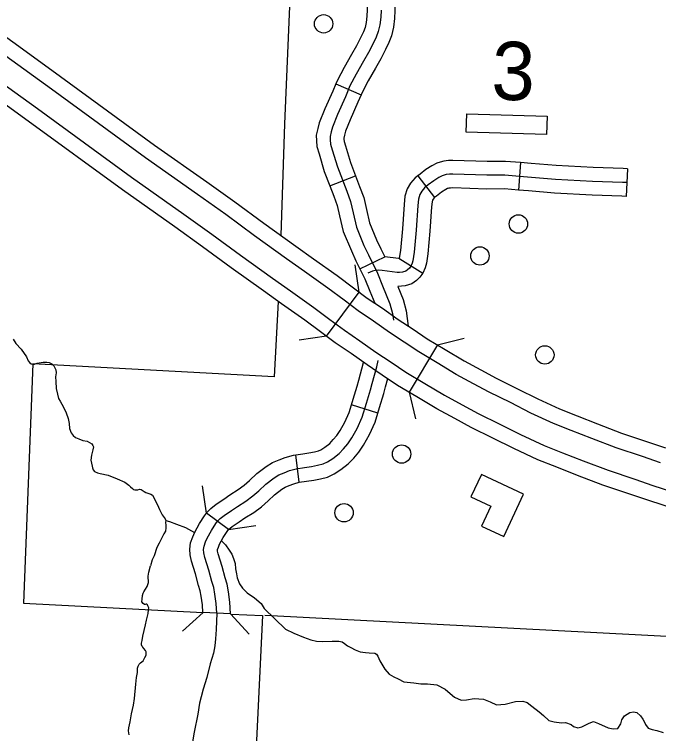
# Model space of a CAD drawing. Extents: x 653372 to 905732, y 627442 to 787275.
# Drawn here: x 663412 to 666917, y 758847 to 762760 of the extents above; entities that cross this region are included whole.
import ezdxf

# ---------------------------------------------------------------- set-up
doc = ezdxf.new("R2010")
doc.units = 0
for name, color, linetype in [('19', 7, 'Continuous'), ('32', 7, 'Continuous'), ('33', 7, 'Continuous'), ('35', 7, 'Continuous'), ('36', 7, 'Continuous'), ('38', 7, 'Continuous'), ('45', 7, 'Continuous'), ('5', 7, 'Continuous'), ('56', 7, 'Continuous'), ('58', 7, 'Continuous'), ('6', 7, 'Continuous')]:
    doc.layers.add(name, color=color, linetype=linetype)

msp = doc.modelspace()

# ---------------------------------------------------------------- linework, layer by layer
at = {"layer": '19'}
for points in [[(663252, 762717.9), (663415.2, 762600.8), (663662.9, 762422.5), (664175.1, 762049), (664458.2, 761848.3), (664611.4, 761739), (664768.3, 761624.5), (664942.4, 761499.1), (665039.1, 761430.2), (665167.9, 761339), (665257.6, 761272.5), (665332, 761216.4), (665414.1, 761161.3), (665500.5, 761099.8), (665580.9, 761046.7), (665657.5, 760994.8), (665755.8, 760936.2), (665858.5, 760874.4), (665950.3, 760825), (666034.1, 760779.8), (666149.2, 760723.4), (666259.3, 760667.5), (666378.6, 760612.8), (666473.3, 760575.2), (666583.9, 760531.6), (666714.6, 760481.9), (666857.2, 760434.4), (666954.2, 760401)], [(666927.3, 760320.4), (666829.9, 760353.9), (666686, 760401.8), (666553.2, 760452.4), (666442.1, 760496.1), (666345.1, 760534.6), (666222.3, 760590.9), (666111.2, 760647.4), (665995.3, 760704.2), (665910, 760750.1), (665816.4, 760800.5), (665712.1, 760863.3), (665611.8, 760923), (665533.6, 760976.1), (665452.5, 761029.7), (665365.7, 761091.4), (665282.7, 761147.1), (665206.7, 761204.5), (665118, 761270.2), (664989.8, 761360.9), (664892.9, 761430), (664718.4, 761555.7), (664561.7, 761670.1), (664409, 761779), (664125.5, 761980), (663613.1, 762353.7), (663365.6, 762531.7)], [(663289.7, 762426.2), (663536.8, 762248.4), (664049.6, 761874.4), (664333.6, 761673.1), (664485.6, 761564.7), (664642.1, 761450.4), (664817.2, 761324.3), (664914.5, 761255), (665041.7, 761164.9), (665128.8, 761100.4), (665207.2, 761041.2), (665291.8, 760984.4), (665378.9, 760922.5), (665461.2, 760868.1), (665542, 760813.3), (665645.3, 760751.7), (665752.1, 760687.5), (665848.4, 760635.7), (665935.8, 760588.6), (666053.2, 760531), (666165.8, 760473.8), (666294, 760415.1), (666394.3, 760375.2), (666506.3, 760331.1), (666642.4, 760279.3), (666788.2, 760230.8), (666886.2, 760197), (667134.5, 760117)], [(667108.6, 760036), (666859.3, 760116.4), (666761, 760150.3), (666613.8, 760199.2), (666475.6, 760251.9), (666363, 760296.2), (666260.6, 760336.9), (666128.8, 760397.3), (666015.2, 760455), (665896.9, 760513), (665808.1, 760560.8), (665710, 760613.6), (665601.7, 760678.8), (665496.4, 760741.5), (665413.9, 760797.4), (665330.9, 760852.4), (665243.5, 760914.5), (665157.9, 760971.9), (665077.9, 761032.3), (664991.9, 761096), (664865.3, 761185.7), (664767.7, 761255.2), (664592.2, 761381.6), (664435.8, 761495.7), (664284.4, 761603.8), (664000, 761805.4), (663486.9, 762179.6), (663240.1, 762357.1)]]:
    msp.add_lwpolyline(points, dxfattribs=at)
at = {"layer": '32'}
for p, q in [((665160.9, 762381.1), (665298.6, 762321.4)), ((666166.4, 761953.4), (666154.8, 761803.9)), ((665128.6, 761826.9), (665268.6, 761880.8)), ((665606.5, 761881.7), (665698, 761762.8)), ((665292.4, 761374.5), (665427.1, 761440.4)), ((665509, 761430.4), (665634.8, 761352.3)), ((665389.2, 760590.1), (665246, 760634.6)), ((664961.8, 760214.6), (664943, 760363.4)), ((664576.1, 759956.4), (664456.3, 760045.6)), ((664588.3, 759498.1), (664437.5, 759505.3))]:
    msp.add_line(p, q, dxfattribs=at)
for points in [[(665480.6, 762842.2), (665481, 762834.1), (665481.8, 762781.6), (665479.9, 762738.1), (665474.6, 762689.5), (665463.4, 762643.9), (665448.9, 762606.7), (665431.5, 762569.2), (665405, 762517.3), (665376.8, 762467.6), (665337, 762398.7), (665305.8, 762338.2), (665298.6, 762321.4)], [(665330.8, 762834.4), (665331.1, 762829.1), (665331.8, 762783.8), (665330.2, 762749.6), (665326.5, 762715.5), (665320.1, 762689.2), (665310.9, 762665.6), (665296.6, 762634.9), (665272.9, 762588.4), (665246.6, 762542.1), (665205.4, 762470.6), (665170.2, 762402.5), (665160.9, 762381.1)], [(665406.8, 762782.7), (665405.1, 762743.8), (665400.5, 762702.5), (665391.8, 762666.5), (665379.9, 762636.2), (665364, 762602), (665339, 762552.8), (665311.7, 762504.8), (665271.2, 762434.7), (665238, 762370.3), (665212.7, 762311.8), (665170.8, 762215.9), (665141.9, 762146.9), (665135.6, 762120.8), (665129.3, 762094.6), (665129.9, 762077), (665131.9, 762054.4), (665141.4, 762022.9), (665169.4, 761929.8), (665220.3, 761797.5), (665240.5, 761741.4), (665254.6, 761680.6), (665273.1, 761602.1), (665314.1, 761503), (665338.3, 761451.4), (665387.3, 761351.1), (665415.3, 761282.1), (665455.3, 761184.5), (665469.3, 761132.6), (665474.4, 761096.1)], [(665160.9, 762381.1), (665143.9, 762341.7), (665101.9, 762245.4), (665070.3, 762170.3), (665062.7, 762138.2), (665054, 762102.3), (665055, 762072.4), (665057.9, 762040.1), (665069.6, 762001.3), (665098.3, 761905.5), (665128.6, 761826.9)], [(665298.6, 762321.4), (665281.4, 762281.9), (665239.8, 762186.4), (665213.4, 762123.5), (665208.5, 762103.3), (665204.6, 762086.9), (665204.8, 762081.7), (665205.9, 762068.8), (665213.3, 762044.4), (665240.4, 761954.1), (665268.6, 761880.8)], [(666166.4, 761953.4), (666083.3, 761959.8), (665983.7, 761959.2), (665797.9, 761965.3), (665774.8, 761964.5), (665748.4, 761961.8), (665729.2, 761956.6), (665710, 761950.7), (665683.2, 761936), (665650.7, 761914.9), (665619, 761891.3), (665606.5, 761881.7)], [(665268.6, 761880.8), (665290.5, 761823.7), (665312.6, 761762.7), (665327.6, 761697.7), (665344.7, 761625.2), (665382.7, 761533.2), (665405.9, 761483.8), (665427.1, 761440.4)], [(666160.6, 761878.6), (666080.7, 761884.8), (665982.7, 761884.1), (665798, 761890.3), (665780.1, 761889.6), (665762, 761887.8), (665750, 761884.6), (665739.3, 761881.3), (665721.7, 761871.6), (665693.6, 761853.3), (665664.2, 761831.5), (665644, 761815.9), (665629.1, 761798.4), (665618.4, 761780.2), (665610.5, 761755.2), (665607, 761719.4), (665598.3, 761586.6), (665586.9, 761466.6), (665580.1, 761419.6), (665576.6, 761405.3), (665569.6, 761389.9), (665562.1, 761379.4), (665551.6, 761369.5), (665541.9, 761362.6), (665523.7, 761357.2), (665507.5, 761355.3), (665493.8, 761356.3), (665413.9, 761366.5), (665394.8, 761368.3), (665375, 761366.5), (665361.1, 761362.7), (665334.5, 761352.7)], [(665606.5, 761881.7), (665592, 761870.5), (665567.8, 761842), (665549.5, 761810.9), (665536.6, 761770.4), (665532.3, 761725.5), (665523.5, 761592.6), (665512.4, 761475.6), (665506.3, 761433.7), (665505.6, 761430.6), (665509, 761430.4)], [(665128.6, 761826.9), (665150, 761771.3), (665168.5, 761720.1), (665181.6, 761663.6), (665201.5, 761579.1), (665245.4, 761472.7), (665270.6, 761419), (665315.1, 761328)], [(666154.8, 761803.9), (666078, 761809.8), (665981.8, 761809.1), (665798.1, 761815.2), (665785.3, 761814.8), (665775.7, 761813.8), (665770.7, 761812.5), (665768.7, 761811.8), (665760.2, 761807.2), (665736.5, 761791.8), (665709.5, 761771.6), (665698, 761762.8)], [(665698, 761762.8), (665696, 761761.3), (665690.5, 761754.8), (665687.3, 761749.4), (665684.4, 761740.1), (665681.8, 761713.3), (665673, 761580.6), (665661.4, 761457.7), (665653.8, 761405.4), (665647.9, 761380.7), (665634.8, 761352.3), (665618.9, 761329.9), (665599.2, 761311.3), (665575.1, 761294.3), (665539, 761283.5), (665497.8, 761278.6)], [(665508.9, 761430.4), (665501.3, 761431), (665427.1, 761440.4)], [(665315.1, 761328), (665318.8, 761320.5), (665345.9, 761253.8), (665372.3, 761189.4)], [(665497.8, 761278.6), (665526.5, 761208.5), (665542.9, 761147.6), (665554.7, 761064)], [(664512.9, 759501.4), (664509.5, 759554.9), (664503.1, 759605.8), (664496.3, 759641.6), (664486.2, 759673.6), (664469.8, 759735.9), (664448.2, 759805.5), (664442.5, 759829.5), (664441.5, 759847.7), (664443.7, 759866.7), (664452.3, 759889.4), (664460.6, 759909.3), (664484.1, 759952.2), (664508.2, 759989.5), (664517.3, 760001.9), (664531.2, 760016.5), (664553.1, 760034.1), (664593.5, 760060.6), (664625, 760082.6), (664671.9, 760112.1), (664709.1, 760139.5), (664741.7, 760167.9), (664779.2, 760204), (664824.6, 760237.9), (664851.2, 760255.3), (664879.3, 760266.4), (664908.9, 760277.4), (664945.7, 760288.1), (664991.3, 760293.9), (665028, 760299.9), (665061.4, 760306.9), (665091.8, 760313.9), (665115.9, 760325), (665144.9, 760344), (665178.2, 760369.9), (665202.7, 760396.1), (665225.7, 760423.2), (665248.1, 760455.8), (665277.4, 760507.2), (665303.8, 760567.8), (665327.4, 760644), (665350.2, 760717.8), (665358.4, 760751.6), (665383.3, 760842), (665392.2, 760876.7)], [(665246, 760634.6), (665255.8, 760666.2), (665277.9, 760737.6), (665285.8, 760770.3), (665311.8, 760864.9)], [(665389.2, 760590.1), (665399.1, 760621.8), (665422.6, 760697.9), (665431, 760732.9), (665443.4, 760777.9)], [(664943, 760363.4), (664980.5, 760368.1), (665014.3, 760373.7), (665045.4, 760380.1), (665067.3, 760385.2), (665079.4, 760390.8), (665101.3, 760405.1), (665127.5, 760425.5), (665146.8, 760446.1), (665166.1, 760468.8), (665184.5, 760495.6), (665210.2, 760540.8), (665233.3, 760594), (665246, 760634.6)], [(664961.8, 760214.6), (665002.1, 760219.7), (665041.7, 760226.2), (665077.5, 760233.6), (665116.2, 760242.5), (665152.3, 760259.2), (665188.5, 760282.9), (665228.9, 760314.4), (665258.7, 760346.2), (665285.4, 760377.5), (665311.7, 760415.9), (665344.5, 760473.6), (665374.2, 760541.6), (665389.2, 760590.1)], [(664456.3, 760045.6), (664459.6, 760050.1), (664480.3, 760071.8), (664509, 760094.8), (664551.4, 760122.7), (664583.6, 760145.1), (664629.6, 760174.1), (664662.2, 760198.1), (664691, 760223.2), (664730.6, 760261.3), (664781.6, 760299.4), (664816.6, 760322.3), (664852.5, 760336.4), (664885.3, 760348.6), (664930.4, 760361.8), (664943, 760363.4)], [(664576.1, 759956.4), (664597.2, 759973.3), (664635.5, 759998.5), (664666.5, 760020.1), (664714.1, 760050.1), (664756.1, 760081), (664792.3, 760112.5), (664827.8, 760146.7), (664867.6, 760176.4), (664885.8, 760188.3), (664906.1, 760196.3), (664932.6, 760206.1), (664961, 760214.5), (664961.8, 760214.6)], [(664437.5, 759505.3), (664434.8, 759547.8), (664429, 759594.1), (664423.5, 759623.2), (664414.1, 759652.8), (664397.7, 759715.3), (664375.7, 759785.8), (664368, 759818.7), (664366.3, 759849.8), (664370.2, 759884.5), (664382.6, 759917.2), (664393, 759941.9), (664419.6, 759990.5), (664446.4, 760032), (664456.3, 760045.6)], [(664588.3, 759498.1), (664584.2, 759561.9), (664577.3, 759617.5), (664569.1, 759660), (664558.2, 759694.5), (664541.9, 759756.6), (664520.6, 759825.3), (664517, 759840.2), (664516.7, 759845.6), (664517.1, 759848.9), (664521.9, 759861.6), (664528.3, 759876.6), (664548.6, 759913.8), (664576.1, 759956.4)]]:
    msp.add_lwpolyline(points, dxfattribs=at)
at = {"layer": '33'}
msp.add_lwpolyline([(664512.9, 759501.4), (664510.1, 759413.2), (664506.5, 759362.5), (664503.3, 759324.8), (664495.9, 759284.5), (664477.7, 759226.7), (664459, 759151.7), (664439.9, 759089.1), (664428.4, 759046.7), (664419.8, 759011.9), (664409.8, 758953.1), (664390.4, 758855.5), (664381.9, 758802.2)], dxfattribs=at)
at = {"layer": '35'}
for points in [[(663405.9, 760993.1), (663419.4, 760968.8), (663448.3, 760938.8), (663477.4, 760897.1), (663486.4, 760874.2), (663496.5, 760864.8), (663503.5, 760859.4), (663515, 760855.8), (663536.6, 760862.3), (663569.1, 760867.1), (663589.2, 760867.2), (663601.4, 760865.5), (663614.8, 760858.6), (663626.1, 760847.9), (663632.3, 760836.7), (663637.1, 760825), (663638.5, 760808.7), (663636, 760787.9), (663637.1, 760762.6), (663639.9, 760724.3), (663645.5, 760694.4), (663651.8, 760669.6), (663661.1, 760655.7), (663679.5, 760622.1), (663694.1, 760591.2), (663704.2, 760561.2), (663709.9, 760533.1), (663712.3, 760506.5), (663720.7, 760483.6), (663732.5, 760468.4), (663745.2, 760458.3), (663762.4, 760451.3), (663784.2, 760442.2), (663808.6, 760436.9), (663821, 760430.5), (663832.4, 760423), (663839.3, 760415), (663841.6, 760406.6), (663838.5, 760390.5), (663832.7, 760369.3), (663831.3, 760361.5)], [(663831.3, 760361.5), (663827.2, 760335.1), (663830.6, 760318.8), (663834.6, 760302.5), (663836.3, 760292.8), (663840.5, 760282.3), (663847.3, 760273), (663864.6, 760266), (663879.3, 760261.7), (663922.4, 760252), (663970.4, 760233.7), (664012.5, 760214.3), (664035.4, 760198.7), (664043.5, 760189.4), (664053.6, 760180.7), (664060.6, 760175.3), (664067, 760173.2), (664083.1, 760172.7), (664093, 760176.3), (664102, 760175.3), (664117.2, 760164.5), (664127.4, 760159), (664142.7, 760152.8), (664153.6, 760149.2), (664163.2, 760143.1), (664170.6, 760131.8), (664176.7, 760119.4), (664191.4, 760091.1), (664200.7, 760065.2), (664216.7, 760036.8), (664232.9, 760015.6), (664235.8, 760005.8), (664234.9, 759995.5), (664235.7, 759980.6), (664235.3, 759966.3), (664233.4, 759948.3), (664225.2, 759933), (664212.8, 759907.5), (664199.1, 759882.6), (664186.7, 759859), (664172.5, 759814.4), (664162.1, 759792), (664152.2, 759760.1)], [(664235.8, 760005.8), (664255.1, 760001.6), (664293.5, 759986.2), (664342.8, 759968.6), (664392.2, 759940.4)], [(664537.8, 759897.1), (664559.9, 759873.7), (664581, 759844.5), (664594.6, 759822.8), (664603.6, 759799.2), (664612.5, 759772.4), (664615.5, 759742.5), (664619.8, 759715.2), (664623.5, 759693.4), (664636.1, 759662), (664652.2, 759638.2), (664679.3, 759612.8), (664718.6, 759585), (664753.9, 759554.2), (664771.1, 759528.3), (664887.4, 759415.8)], [(664035.5, 758839.9), (664033.1, 758861.3), (664034.1, 758877.9), (664041.4, 758911.4), (664049.1, 758954.6), (664059.9, 759002), (664064.9, 759038.5), (664073.2, 759116.6), (664076.8, 759151.5), (664081.4, 759178.8), (664081.7, 759203.5), (664085.5, 759214.4), (664090.5, 759224.5), (664097.5, 759231.5), (664104.9, 759236.8), (664112.3, 759243.4), (664116.8, 759249.7), (664121.3, 759260.2), (664128.1, 759274.1), (664129.7, 759283), (664128.2, 759291.5), (664125.9, 759299.3), (664116, 759309.8), (664110.7, 759316.8), (664107.4, 759321.5), (664103.4, 759330.2), (664102.8, 759338.3), (664107.1, 759352.7), (664110.8, 759376.8), (664124.6, 759439.1), (664130.9, 759464.5), (664140, 759499.6), (664142.3, 759520), (664142.7, 759531), (664138.7, 759541.4), (664135.5, 759547), (664131.7, 759550.1), (664128.4, 759551), (664123.6, 759549.9), (664120.2, 759549.2), (664112.3, 759554.5), (664105.8, 759564.1), (664107, 759578.5), (664108.9, 759597.6), (664111.8, 759610.3), (664115.9, 759618.3), (664124.8, 759631.7), (664135.1, 759646.3), (664137.1, 759657.4), (664141.3, 759669.5), (664140.6, 759703.4), (664144.2, 759724.5), (664152.2, 759760.1)], [(664885.4, 759417.3), (664887.4, 759415.8), (664932.6, 759392.4), (664984.5, 759372.1), (665024.1, 759357.3), (665055, 759349.9), (665087.9, 759347.6), (665141.7, 759349.3), (665178, 759350.1), (665195.3, 759346.4), (665208.6, 759336.9), (665223.8, 759324.1), (665241.7, 759315.2), (665266.5, 759302.1), (665293.4, 759291.6), (665322.4, 759288.8), (665342.4, 759286.9), (665373.1, 759283.8), (665381.4, 759278.4), (665390.2, 759268.4), (665400.4, 759243.5), (665426.8, 759196.8), (665451.9, 759169.5), (665477.4, 759155.1), (665500.3, 759144), (665531.6, 759127.6), (665585.5, 759122.1), (665623.5, 759117), (665653.9, 759117.4), (665659.8, 759117)], [(665659.8, 759117), (665710.9, 759112.2), (665755.5, 759088.6), (665770.4, 759076.2), (665807.3, 759044.2), (665842.6, 759028.2), (665871.5, 759030.3), (665914.5, 759038), (665965.2, 759034.5), (666001.6, 759020.4), (666035.9, 759003.5), (666081.8, 759006.1), (666139, 759022.3), (666178.8, 759023.1), (666202.5, 759016.4), (666227.8, 758996.7), (666267.6, 758964.7), (666290.9, 758945), (666319.9, 758918.3), (666348.6, 758910.5), (666389.2, 758905.3), (666411.1, 758906.6), (666440.7, 758896.8), (666454.3, 758885.4), (666476.9, 758877.7), (666499, 758884), (666539.4, 758903.7), (666563.1, 758912), (666589.6, 758902.2), (666642.7, 758878.7), (666669.3, 758872), (666695.3, 758875.2), (666711, 758899.6), (666717.6, 758922.3), (666732.2, 758942.7), (666760.6, 758961.8), (666780.6, 758965.2), (666798.4, 758961.7), (666818.7, 758943.1), (666832.2, 758925.8), (666838.7, 758912.7), (666845.2, 758896.5), (666860.5, 758877.2), (666882.2, 758868.6), (666907.9, 758863.8), (666941.4, 758852.8)]]:
    msp.add_lwpolyline(points, dxfattribs=at)
at = {"layer": '36'}
for p, q in [((665288.4, 761249.3), (665266.6, 761397.7)), ((665109.3, 761008.6), (665288.4, 761249.3)), ((665109.3, 761008.6), (664960.9, 760986.9)), ((665713.8, 760961.2), (665559.1, 760704.2)), ((665713.8, 760961.2), (665859.3, 760997.4)), ((665559.1, 760704.2), (665595.3, 760558.6))]:
    msp.add_line(p, q, dxfattribs=at)
at = {"layer": '38'}
for points in [[(664456.3, 760045.6), (664434.6, 760194)], [(664725.1, 759977.8), (664576.6, 759956)], [(664327.4, 759404.4), (664438.4, 759505.3)], [(664588.3, 759498.1), (664689.1, 759387.1)]]:
    msp.add_lwpolyline(points, dxfattribs=at)
at = {"layer": '45'}
msp.add_line((666747.4, 761919.2), (666739.9, 761769.4), dxfattribs=at)
for points in [[(666223, 761948.5), (666166.4, 761953.4)], [(666747.4, 761919.2), (666723.9, 761920.4), (666561.5, 761926.3), (666360.6, 761936.7), (666223, 761948.5)], [(666743.6, 761844.3), (666720.6, 761845.4), (666558.2, 761851.4), (666355.5, 761861.9), (666160.6, 761878.6)], [(666210.1, 761799.1), (666154.8, 761803.9)], [(666739.9, 761769.4), (666717.4, 761770.5), (666554.9, 761776.5), (666350.3, 761787), (666210.1, 761799.1)]]:
    msp.add_lwpolyline(points, dxfattribs=at)
at = {"layer": '5'}
msp.add_lwpolyline([(668631.2, 759288.8), (664775.3, 759488.5)], dxfattribs=at)
at = {"layer": '56'}
msp.add_lwpolyline([(665870.3, 762119.1), (665873.3, 762219.1), (666310.6, 762206), (666307.6, 762106)], close=True, dxfattribs=at)
for centre in [(665094.6, 762708.3), (666154.5, 761619.3), (665944.8, 761445.4), (666298.2, 760907.3), (665518.8, 760367.8), (665205.4, 760048.4)]:
    msp.add_circle(centre, 50, dxfattribs=at)
at = {"layer": '58'}
msp.add_lwpolyline([(666182.8, 760149), (665952.8, 760256.7), (665895.9, 760135.3), (666004.8, 760084.4), (665953.9, 759975.7), (666075.1, 759918.9)], close=True, dxfattribs=at)
at = {"layer": '6'}
for points in [[(664987.9, 764679.4), (664882.3, 762163.4), (664862.3, 761556.8)], [(664847.7, 761198.1), (664824.6, 760787.7), (663512.4, 760857.9)], [(663512.4, 760857.9), (663460.6, 759556.5), (664437.5, 759505.3)], [(664590.8, 759497.4), (664762.5, 759489.1), (664635.7, 756845.2), (663939.9, 756878.5)]]:
    msp.add_lwpolyline(points, dxfattribs=at)

# ---------------------------------------------------------------- texts
at = {"layer": '56'}
msp.add_text('3', height=316.8, rotation=358.28, dxfattribs=at).set_placement((666004.8, 762297.2))

doc.saveas('drawing.dxf')
